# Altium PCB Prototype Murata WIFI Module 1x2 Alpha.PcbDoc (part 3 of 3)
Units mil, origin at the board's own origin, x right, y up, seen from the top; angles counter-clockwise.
Board outline 708.66 x 1594.49 mil, 6 copper layers (Component Side, Ground Plane (GND), Inner Layer 1, Inner Layer 2, Power Plane (VCC), Solder Side), stack 20.279 mil thick; 197 components, 116 nets, 943 pads, 479 vias.
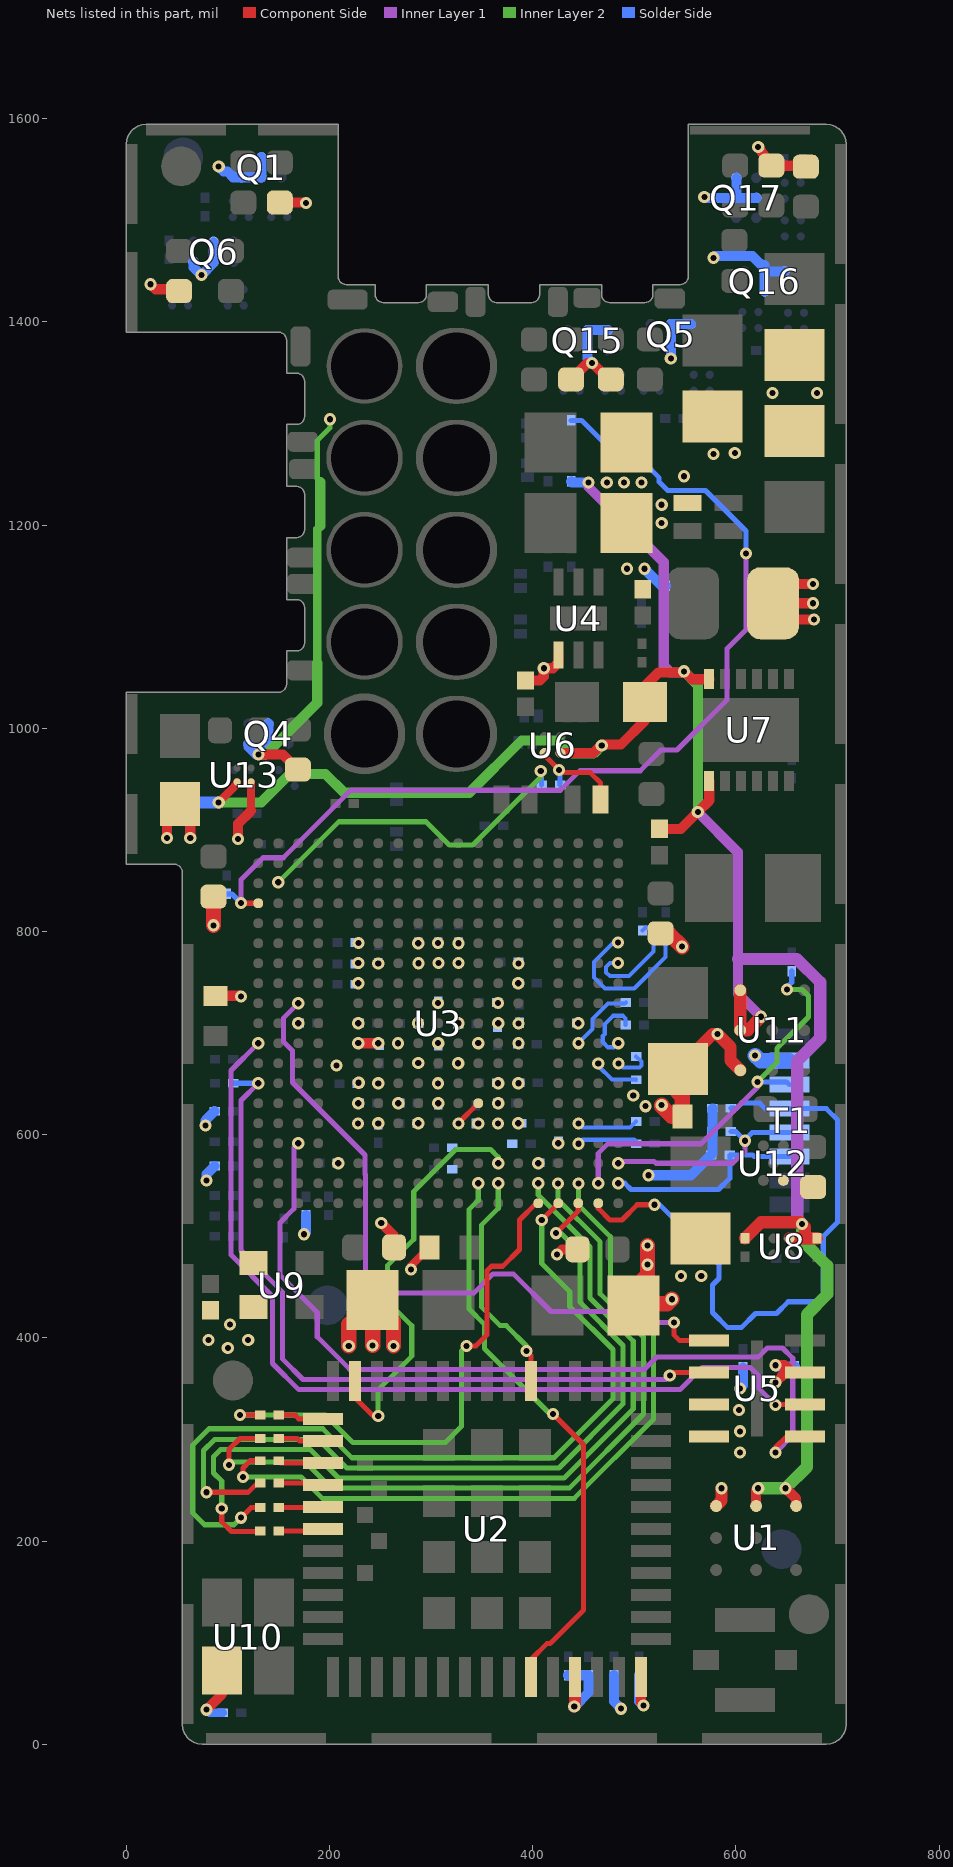
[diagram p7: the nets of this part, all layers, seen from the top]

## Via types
v1: diameter 12, hole 6, Component Side to Solder Side, tented both sides, 479 vias

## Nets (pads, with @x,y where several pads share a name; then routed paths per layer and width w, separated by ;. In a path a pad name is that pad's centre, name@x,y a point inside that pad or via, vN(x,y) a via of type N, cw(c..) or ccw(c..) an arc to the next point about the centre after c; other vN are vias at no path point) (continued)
RX_CLK_N: C54.2 U3.J1 | length 69.2
  Solder Side w4: v1(484.29,690) 480.29,686 474,686 469,691 469,697 471,699 471,709 479,717 489,717 491.54,714.46 C54.2@491.54,708
RX_CLK_P: C53.2 U3.J3 | length 69.1
  Solder Side w4: v1(445,690) 459,704 459,713.97 474.03,729 490.68,729 C53.2@491.68,730
RX_N: C49.2 U3.P1 | length 160.6
  Solder Side w4: v1(484,789) 479.38,789 460.36,769.97 460.36,754.67 471.03,744 500,744 530.94,774.94 C49.2@530.94,800.94
RX_P: C48.2 U3.N1 | length 111.1
  Solder Side w4: v1(484,769) 476.36,769 472.36,765 472.36,759.64 476,756 494.91,756 519,780.09 519,783 519,801 516,804 511.11,804 C48.2@508.06,800.94
SDIO_CLK: R1.1 U3.A3 | length 791
  Component Side w5: v1(79,248) 120,248 129,257 R1.1@131.94,257 ; v1(423,503) 444.88,524.88 U3.A3@444.88,532.48
  Inner Layer 2 w5: v1(79,248) 76,251 76,289 87,300 189,300 217,272 426,272 489,335 489,392.57 446.5,435.07 446.5,484.5 428,503 v1(423,503)
SDIO_CMD: R2.1 U3.B3 | length 736.5
  Component Side w5: v1(115,263) 115,272 122,279 R2.1@131.94,279
  Inner Layer 2 w5: v1(115,263) 172,263 193,242 441,242 519,320 519,405 476.5,447.5 476.5,499.5 445,531 v1(445,552)
SDIO_D0: R3.1 U3.A4 | length 829.4
  Component Side w5: v1(113,223) 123,233 R3.1@131.94,233 ; v1(409,516) 425.2,532.2 U3.A4@425.2,532.48
  Inner Layer 2 w5: v1(113,223) 106,216 77,216 65.5,227.5 65.5,294.5 81.5,310.5 193.5,310.5 222,282 421,282 479,340 479,388.43 436.5,430.93 436.5,445.64 409,473.14 v1(409,516)
SDIO_D1: R4.1 U3.B4 | length 762.5
  Component Side w5: v1(101,275) 101,290 112,301 R4.1@131.94,301
  Inner Layer 2 w5: v1(101,275) 104,278 176,278 202,252 436,252 509,325 509,400.86 466.5,443.36 466.5,494.5 425,536 v1(425,552)
SDIO_D2: R5.1 U3.A5 | length 519.4
  Component Side w5: v1(112,324) R5.1@131.94,324 ; v1(335,392) 344,392 355,403 355,452 355,455 355,466 359.5,470.5 370.5,470.5 387,487 387,516 403.48,532.48 U3.A5@405.51,532.48
  Inner Layer 2 w5: v1(112,324) 196,324 223,297 314,297 330,313 330,387 v1(335,392)
SDIO_D3: R6.1 U3.B5 | length 826
  Component Side w5: v1(94,232) 94,219 103.5,209.5 131.44,209.5 R6.1@131.94,210
  Inner Layer 2 w5: v1(94,232) 94,259 86,267 86,283 93,290 181,290 209,262 431,262 499,330 499,396.72 456.5,439.22 456.5,489.5 405.51,540.49 v1(405.51,552.17)
SPI_FLASH_CLK: R20.2 U3.G19 U5.6 | length 750.8
  Component Side w5: v1(535,363) 537.75,365.75 U5.6@573.76,365.75
  Inner Layer 1 w5: v1(129.92,650.59) 113,633.67 113,485.86 154,444.86 154,379 174,359 492,359 531,359 v1(535,363)
  Solder Side w5: R20.2@105.51,650.59 v1(129.92,650.59)
SPI_FLASH_CS_N: U3.D17 U5.1 | length 845.9
  Component Side w5: v1(639,287) 639,292 649.76,302.76 U5.1@668.24,302.76
  Inner Layer 1 w5: v1(169.29,591.54) 165,587.24 165,527 151.5,513.5 151.5,461.5 188,425 188,401 220,369 510,369 522,381 622,381 631,390 646,390 656,380 656,304 v1(639,287)
SPI_FLASH_MISO: U3.J19 U5.2 | length 909.4
  Component Side w5: v1@639.25,334.25 U5.2@668.24,334.25
  Inner Layer 1 w5: v1(129.92,689.96) 103,663.04 103,481.72 144,440.72 144,374.86 169.86,349 518.14,349 545,349 567,371 614,371 623,362 623,350 v1(639,334)
SPI_FLASH_MOSI: U3.L17 U5.5 | length 697.4
  Component Side w5: v1(539,415) 539,403 544.76,397.24 U5.5@573.76,397.24
  Inner Layer 1 w5: v1(169.29,729.33) 154.58,714.62 154.58,691.58 163.58,682.58 163.58,651.38 234.98,579.98 234.98,561 235.5,560.48 235.5,457.5 249,444 294,444 342,444 361,463 381,463 418,426 481,426 492,415 v1(539,415)
TCK: R32.1 T1.3 U3.B2 | length 400.1
  Inner Layer 1 w5: v1(464.57,552.17) 464.57,581.57 474,591 565.71,591 621.23,646.53 v1(621.23,652)
  Inner Layer 2 w5: v1(621.23,652) 640.31,671.07 640.31,684.69 671.5,715.88 671.5,736.5 665.06,742.94 v1(650.42,742.94)
  Solder Side w5: v1(621.23,652) 649.97,652 T1.3@652.76,649.21 ; v1(650.42,742.94) 650.42,745.42 655,750 R32.1@655,760.94
TDI: R28.2 T1.5 U3.C1 | length 205.5
  Inner Layer 1 w5: v1(484.25,571.85) 485.9,573.5 519.59,573.5 521.24,571.85 596.85,571.85 609,584 v1(609,594)
  Solder Side w5: R28.2@595.06,603 598.84,603 600,603 608.5,594.5 615.97,601.97 T1.5@652.76,601.97
TDO: R29.2 T1.6 U3.B1 | length 199.3
  Solder Side w5: v1(484.25,552.17) 490.73,552.17 496.9,546 523,546 583,546 594.06,557.05 R29.2@594.06,580.05 616.38,580.05 618.09,578.35 T1.6@652.76,578.35
TMS: R27.2 T1.4 U3.A2 | length 654.5
  Component Side w5: U3.A2@464.57,532.48 464.57,527.43 476,516 488,516 503,531 v1(520,531)
  Solder Side w5: v1(520,531) 525,531 583.5,472.5 583.5,458.5 576.96,451.96 576.96,425.04 592,410 605.38,410 619.38,424 640,424 651.5,435.5 678.5,435.5 686,443 686,499.77 700.1,513.87 700.1,614.59 689.1,625.59 T1.4@652.76,625.59 ; R27.2@595.06,626 600.71,626 605.71,631 623.5,631 629,625.5 652.67,625.5 T1.4@652.76,625.59 ; 677.59,625.59 T1.4@652.76,625.59
TX_CLK_N: C47.2 U3.H2 | length 45.3
  Solder Side w4: v1(464.57,670.03) 464.57,667.54 477.94,654.17 481,654.17 501.63,654.17 C47.2@501.8,654
TX_CLK_P: C46.2 U3.H1 | length 36.1
  Solder Side w4: v1(484.57,670.17) 488.73,666 505,666 507,668 507,671.8 C46.2@501.8,677
TX_N: C45.2 U3.E3 | length 61
  Solder Side w4: v1(445,611) 449,607 495.89,607 C45.2@501.89,613
TX_P: C43.2 U3.D3 | length 61.5
  Solder Side w4: v1(445,591) 449,595 500,595 501.98,593.02 C43.2@501.98,591
V1P2: C18.2 C19.2 C20.2 C21.2 C22.2 C23.2 C24.2 C25.2 C27.2 C28.2 C29.2 C30.2 C31.2 C32.2 C33.2 C78.2 U3.E8 U3.E14 U3.F7 U3.G6 U3.G10 U3.G14 U3.H9 U3.H11 U3.J8 U3.J10 U3.J12 U3.K9 U3.K11 U3.L10 U3.M6 U3.N9 U3.N10 U3.N11 U3.N14 U3.P9 U3.P10 U3.P11 U11.A1 | length 302.8
  Component Side w8: U3.N14@226.85,768.7 U3.N14@228.35,768.7
  Component Side w10: U3.G14@228.35,650.59 v1(228.8,651.04) ; U3.N14@228.35,768.7 v1(228.35,768.85) ; C32.2@519.6,664.6 C32.2@543,664.6
  Component Side w12: C32.2@543,664.6 577.36,698.95 v1(582.05,698.95) 594.86,686.14 594.86,672.86 602,665.72 U11.A1@604.33,663.39 U11.A1@604,663.72
  Component Side w15: v1(513,491) v1(513,472) 513,462 499.4,448.4 C78.2@499.4,432 500.9,433.5 532.5,433.5 v1(537,438) ; v1(527,629) 527,628 537,618 C31.2@547.32,618 547.32,637 543,641.32 C32.2@543,664.6
  other v1: 228,611 346.46,611.04 511,628 366.09,630.91 499,638.67 307,650.5 385.91,650.59 207,668 287.4,670.4 326.72,670.28 267.54,689.96 307.05,690 346.5,690 287.15,709.65 326.85,709.65 307,729.42 385.81,749 287.7,768.7 307.39,769 327,768.93 287.4,788.4 307,788.47 326.89,788.39
V1P8: C1.2 C26.2 C51.2 C73.2 C74.2 C75.2 U1.A1 U2.38 U3.E7 U3.E9 U3.F8 U10.4 | length 196.3
  Component Side w5: U3.E9@327.05,611.5 U3.F8@346.46,630.91
  Component Side w10: v1(79,34) 94.41,49.41 U10.4@94.41,72.54 ; U3.E9@326.77,611.22 327.05,611.5 U3.E9@327.05,611.22
  Component Side w12: v1(441,37) 441.61,37.61 U2.38@441.61,66.33 ; U1.A1@580.63,234.5 586,239.87 v1(586,252)
  Solder Side w8: v1(79,34) 82,31 C1.2@94.94,31
  Solder Side w10: C74.2@435,67.94 C75.2@455,67.94 455,51 v1(441,37)
  other v1: 327,611 366,611
V1P8_19P2MHZ: U2.36 U3.B8 | length 558.1
  Component Side w5: U2.36@398.31,66.33 398.31,83.31 414,99 417,99 450,132 450,295 v1(420,325)
  Inner Layer 2 w5: v1(346.46,552.17) 346.46,535.46 337.5,526.5 337.5,428.36 352.5,413.36 352.5,389.5 v1@417,325
V2P5: C59.2 C63.2 C64.2 C65.2 C82.2 L5.2 U3.E6 U3.G7 U3.J6 U12.C3 | length 29.3
  Component Side w10: v1(251,513) 263.69,500.31 C59.2@263.69,489
  other v1: 546,461 566,461 385.83,611.17 366.09,650.59 385.96,689.96
V3P3: C2.2 C3.2 C4.2 C5.2 C6.2 C7.2 C12.1 C13.1 C15.1 C16.2 C17.1 C34.2 C35.2 C36.2 C37.2 C38.2 C44.2 C55.2 C56.2 C57.2 C58.2 C60.2 C61.2 C62.2 C66.2 C67.2 C68.2 C69.2 C70.2 C71.2 C72.2 C95.2 L1.1 R22.1 R26.2 R27.1 R28.1 R29.1 R34.2 T1.2 U2.41 U3.C5 U3.C15 U3.D4 U3.E11 U3.E13 U3.F10 U3.F12 U3.F14 U3.G13 U3.J13 U3.J14 U3.K3 U3.K6 U3.K7 U3.K14 U3.K17 U3.L7 U3.M14 U3.N6 U3.N13 U3.P14 U4.4 U5.3 U5.7 U5.8 U9.1 U9.4 U13.A1 | length 1041
  Component Side w8: 122.89,918.89 U13.A1@122.89,947.11 ; v1(280.32,467.32) 280.32,471 C37.2@298.32,489
  Component Side w10: v1(40,892) 40,912.54 C95.2@53,925.54 63,915.54 v1(63,892) ; C16.2@88,736.68 112.32,736.68 v1(113,736) ; v1(110,891) 110,906 122.89,918.89 ; U3.J14@228.35,689.96 v1(248,689.99) ; v1(248.03,611.16) v1(248.03,611.16) ; v1(366,729.47) U3.L7@366.14,729.33 ; U3.K6@385.83,709.65 v1(385.97,709.5) ; U3.N6@385.83,768.7 v1(386,768.53) ; C2.2@393,1046.99 406.99,1046.99 411,1051 v1(411,1059) 420,1059 425.32,1064.32 U4.4@425.32,1072.17 U4.4@425.32,1067.32 ; v1(424,482) 429,487 C61.2@444.31,487 ; v1@506.57,40.43 U2.41@506.57,66.33 ; v1(639,356) 648.75,365.75 U5.3@668.24,365.75 655.25,365.75 648,373 v1(639,373) ; v1(676,1123) L1.1@636.76,1123 ; v1(676,1142) 655.76,1142 L1.1@636.76,1123 ; v1(677,1107) 652.76,1107 L1.1@636.76,1123
  Component Side w15: v1(85.91,806) C60.2@85.91,834.31 ; v1(219,392) 219,413.4 C38.2@242.6,437 ; v1(242.4,392.4) 242.6,392.4 C38.2@242.6,437 ; v1(263,392) 263,416.6 C38.2@242.6,437 ; C72.2@526,798.12 533.88,798.12 v1(547,785)
  Solder Side w10: v1(78,609) 78,614.06 R34.2@86.94,623 R34.2@86.8,623 ; v1(79,555) 79,561.05 R22.1@86.94,569 ; v1(175,502) 177,504 R26.2@177,520.94 ; C56.2@480,67.94 480,42 v1(487,35) ; C55.2@505,67.94 505,42 v1(509,38) ; v1(514,560) 555.89,560 R29.1@575.94,580.05 576.94,581.06 R28.1@576.94,603 576.94,625.27 R27.1@577.31,625.63 ; v1(604,350) 607,353 C13.1@607,370.94 ; v1(639,373) 640.06,371.94 C12.1@658,371.94
  Solder Side w15: v1(619,678) 624.17,672.83 T1.2@652.76,672.83
  other v1: 604,287 604,308 603,329 100,390 81,398 120,398 102,413 208.66,571.85 405.51,571.85 425.2,591.54 287.4,611.22 228.35,630.91 267.72,630.91 307.09,630.91 248.03,650.53 228.39,690 169.29,709.65 228.35,709.65 366.14,709.64 444.88,709.65 228.36,749 248.03,768.53 228.46,788.5
V3P3_ALWAYS: C41.2 C42.2 C52.2 C77.2 C94.2 R15.2 U1.A2 U1.A3 U6.A2 U7.1 U7.12 U8.A2 U11.A2 U11.A3 U13.A2 | length 2236.6
  Component Side w8: v1(91,927) 109.11,945.11 U13.A2@109.11,947.11
  Component Side w10: U6.A2@427.47,975.63 459.63,975.63 468,984 487,984 510.46,1007.46 C52.2@510.46,1026 510.46,1041.46 524,1055 548,1055 v1(549,1056) 556.77,1048.23 U7.12@573.82,1048.23 ; C77.2@525,900.99 546.08,900.99 v1(562.59,917.5) 573.82,928.73 U7.1@573.82,947.84 ; U1.A2@620,234.5 v1@620,250 ; v1(649,252) 659.37,241.63 U1.A3@659.37,234.5
  Component Side w12: U11.A3@604.33,742.13 U11.A2@604.33,702.76 611.76,702.76 v1@624.73,715.73 ; C42.2@609,498.06 624.74,513.8 v1@663.2,513.8 ; U8.A2@653.06,498.06 668,498.06 ; v1@668,509 668,498.06 ; C41.2@680,498.06 668,498.06
  Inner Layer 1 w10: v1(455,1242) 455,1237.37 529,1163.37 529,1061.37 535.37,1055 548,1055 v1(549,1056) ; v1(562.59,917.5) 602,878.09 602,773 602,738.73 v1(624.73,716)
  Inner Layer 1 w12: 602,773 660,773 683,750 683,695 660.5,672.5 660.5,516.5 v1(665,512)
  Inner Layer 2 w10: v1(91,927) 133,927 161,955 196,955 214.44,936.56 337.56,936.56 389,988 426,988 439,975 460,975 v1(468,983) ; v1@548,1055 v1(549,1056) 562.59,1042.41 v1(562.59,917.5)
  Inner Layer 2 w12: v1(622,252) v1(649,252) 670,273 670,423 690,443 690,471 665,496 v1(665,512)
  Solder Side w10: R15.2@438,1242.94 438.94,1242 v1(455,1242)
  Solder Side w12: C94.2@70.06,927 v1(91,927)
V28P0: C8.2 C9.2 C10.2 C11.2 C39.2 C40.2 D1.2 Q1.2 Q1.3 Q1.6 Q4.2 Q4.3 Q4.6 Q5.2 Q5.3 Q5.6 Q6.2 Q6.3 Q6.6 Q15.2 Q15.3 Q15.6 Q16.2 Q16.3 Q16.6 Q17.2 Q17.3 Q17.6 R9.1 R13.1 R17.1 R18.1 R19.1 R53.1 R54.1 R55.1 | length 1052.9
  Component Side w10: v1(24,1437) 28.87,1432.13 50.2,1432.13 R19.1@52.01,1430.32 ; v1(130.14,974.2) 154.11,974.2 R17.1@169,959.32 ; R9.1@151.13,1517.44 176.56,1517.44 v1(177,1517) ; R53.1@436.69,1343.32 R53.1@437.95,1343.32 454.23,1359.6 v1(458.5,1359.6) 470.7,1347.4 R18.1@476.9,1347.4 ; v1(622,1572) R55.1@635,1553.68 R54.1@668,1553.68
  Inner Layer 2 w5: 191,1242.4 188,1245.4 188,1283.16 200.5,1295.66 v1(200.5,1304.15)
  Inner Layer 2 w8: 188.03,1064 188.03,1196.17
  Inner Layer 2 w10: v1@130.44,974.2 137.2,974.2 188.03,1025.03 188.03,1064 ; 191,1199.15 191,1242.4
  Solder Side w10: Q6.2@66.23,1459.16 66.23,1453.78 v1(74,1446) 85.91,1457.91 Q6.3@85.91,1459.16 ; Q6.3@86,1458.16 Q6.6@86,1477.84 ; v1(91,1553) 96,1548 99.63,1548 105.34,1542.28 Q1.2@113.44,1542.28 Q1.3@133.13,1542.28 Q1.6@133.13,1561.97 ; Q4.2@120.32,984.84 120.32,981.59 v1@127.7,974.2 ; v1@129.75,974.59 Q4.3@140,984.84 Q4.6@140,1004.53 ; v1(458.5,1359.6) 454.06,1364.04 Q15.6@454.06,1372.16 Q15.3@454.06,1391.84 Q15.2@473.75,1391.84 ; v1(510,1157) 526.94,1140.06 R13.1@531,1140.06 ; v1(536,1364) 536.08,1364.08 Q5.6@536.08,1378.16 Q5.3@536.08,1397.84 Q5.2@555.77,1397.84 ; v1(569,1523) 570,1522 Q17.3@600.51,1522 ; v1(578,1463) 579.8,1464.8 606,1464.8 ; 600,1464.8 606,1464.8 ; Q17.2@600.51,1541.68 Q17.3@600.51,1522 ; Q17.6@620.19,1522 Q17.3@600.51,1522 ; Q16.6@628.32,1430 Q16.3@628.32,1449.68 ; 628.32,1455.68 Q16.3@628.32,1452.68 ; Q16.2@648,1449.68 Q16.3@628.32,1449.68 ; 606,1464.8 616.2,1464.8 Q16.3@628.32,1452.68 ; Q16.3@628.32,1449.68 Q16.3@628.32,1452.68
  other v1: 493,1157 527,1202 527,1220 473,1242 490,1242 507,1242 549,1248 578,1270 599,1271 636,1330 680,1330
WAKE_RX: R64.2 U3.U18 | length 340.4
  Inner Layer 2 w5: v1(149.61,848.39) 209.21,908 295,908 318,885 341,885 408,952 v1(408,958)
  Solder Side w5: R64.2@408.89,944 v1@408.89,958
WAKE_RX_PWR: D3.1 R64.1 U6.B2 | length 100.3
  Component Side w5: U6.B2@411.72,975.63 411.72,973.28 413.5,971.5 413.59,971.5 426,959.09 v1(426,959) 428.72,956.28 456.72,956.28 466.78,946.22 D3.1@466.78,930
  Solder Side w5: v1(426,959) 427,958.09 R64.1@427,944
WAKE_TX: R36.2 R63.2 U3.T19 | length 1002.5
  Component Side w5: v1@113.24,827.76 U3.T19@129.92,827.76
  Inner Layer 1 w5: v1(113,828) 113,851 134.5,872.5 154.59,872.5 221.09,939 427.3,939 446.49,958.2 506,958.2 526.3,978.5 542,978.5 591.5,1028 591.5,1078.5 610,1097 v1(610,1172)
  Solder Side w5: R63.2@99,836.94 104.06,836.94 v1(113,828) ; R36.2@438,1303.06 448,1303.06 490.06,1261 510,1261 524.5,1246.5 524.5,1242.41 532.91,1234 570.07,1234 610,1194.07 v1(610,1172)
WIFI_SDIO_CLK: R1.2 U2.19 | length 44.2
  Component Side w5: R1.2@150.06,257 191.89,257 U2.19@193.58,255.31
WIFI_SDIO_CMD: R2.2 U2.18 | length 44.4
  Component Side w5: R2.2@150.06,279 152.09,276.96 U2.18@193.58,276.96
WIFI_SDIO_D0: R3.2 U2.20 | length 43.8
  Component Side w5: R3.2@150.06,233 192.93,233 U2.20@193.58,233.65
WIFI_SDIO_D1: R4.2 U2.17 | length 44.5
  Component Side w5: R4.2@150.06,301 168,301 170.39,298.61 U2.17@193.58,298.61
WIFI_SDIO_D2: R5.2 U2.16 | length 45.1
  Component Side w5: R5.2@150.06,324 166,324 169.73,320.27 U2.16@193.58,320.27
WIFI_SDIO_D3: R6.2 U2.21 | length 44.4
  Component Side w5: R6.2@150.06,210 191.58,210 U2.21@193.58,212
WLAN_EN: U2.14 U3.C7 | length 405.8
  Component Side w5: U2.14@225.08,357.67 225.08,341.01 243.09,323 v1(248,323)
  Inner Layer 2 w5: v1(248,323) 248,349 281,382 281,412 257,436 257,471 283,497 283,544 324.35,585.35 358.65,585.35 366.14,577.86
  other v1: 366.14,571.85
WLAN_IRQ: U2.6 U3.B7 | length 219
  Component Side w5: U2.6@398.31,357.67 398.31,382.69
  Inner Layer 2 w5: v1(366.14,552.17) 366.14,527.5 349.5,510.86 349.5,430.5 368,412 374,412 394,392 v1(394,387)
pads on no net: U1.B1 U1.C1 U1.C2 U1.C3 U2.1 U2.2 U2.8 U2.9 U2.10 U2.11 U2.12 U2.13 U2.25 U2.31 U2.32 U2.39 U2.40 U2.43 U2.44 U2.45 U2.46 U2.51 U2.52 U2.65 U2.66 U2.67 U2.68 U2.69 U3.A8 U3.A9 U3.A11 U3.A12 U3.A13 U3.A14 U3.A15 U3.A16 U3.A17 U3.B9 U3.B10 U3.B11 U3.B12 U3.B13 U3.B14 U3.B15 U3.B16 U3.B17 U3.C2 U3.C9 U3.C10 U3.C11 U3.C12 U3.C13 U3.C14 U3.D1 U3.D2 U3.D18 U3.E1 U3.E2 U3.E17 U3.E18 U3.F1 U3.F3 U3.F17 U3.F19 U3.G1 U3.G2 U3.G3 U3.G17 U3.H3 U3.H7 U3.H14 U3.H17 U3.H18 U3.H19 U3.J2 U3.J17 U3.J18 U3.K2 U3.K18 U3.L1 U3.L2 U3.L3 U3.L6 U3.L14 U3.L18 U3.L19 U3.M1 U3.M2 U3.M3 U3.M7 U3.M13 U3.M17 U3.M18 U3.M19 U3.N2 U3.N3 U3.N17 U3.N19 U3.P3 U3.P6 U3.P19 U3.T10 U3.U10 U3.U19 U3.V6 U3.V7 U3.V8 U3.V9 U3.V12 U3.V13 U3.V14 U3.V15 U3.V18 U3.V19 U3.W5 U3.W6 U3.W8 U3.W9 U3.W11 U3.W12 U3.W14 U3.W15 U4.2 U4.5 U7.8

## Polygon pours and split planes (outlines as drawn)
V1P2 on Component Side "0" (solid, remove dead copper, pour order 14): 553,691 530,691 522,691 516,691 512,687 493,668 493,648 493,627 496,624 514,606 538,606 557,606 558,607 559,608 559,621 559,631 566,638 567,639 572,639 574,641 576,643 576,657 579,660 593,660 605,660 607,662 608,663 608,667 608,670 603,675 602,676 602,685 602,687 595,694 584,705 580,705 567,705 566,704
V3P3 on Component Side "0" (solid, remove dead copper, pour order 15): 561,353 589,353 595,353 599,357 607,357 609,357 611,355 611,345 611,283 609,281 606,278 599,278 571,278 563,286 553,296 553,300 553,351 555,353
V28P0 on Component Side "TopLayer-No Net" (solid, remove dead copper, pour order 21): 632,1395 673,1395 689,1395 691,1393 692,1392 692,1293 692,1267 687,1262 685,1260 632,1260 586,1260 572,1246 572,1237 572,1216 568,1212 567,1211 539,1211 538,1211 535,1208 535,1174 525,1164 524,1163 524,1130 520,1130 514,1124 502,1124 497,1124 477.17,1143.83 475,1146 475,1163 472,1163 462,1173 459,1176 459,1200 459,1306 445,1320 444,1320 381,1320 368,1333 368,1343 368,1359 372,1363 374,1365 389,1365 442,1365 446,1369 449,1369 529,1369 549,1349 554,1344 567,1344 602,1344 608,1350 615,1357 615,1367 615,1390 620,1395
V2P5 on Component Side "Component Side-No Net" (solid, pour order 18): 545,450 575,450 594,469 595,470 595,494 595,500 613,518 621,526 667,526 682,526 689,533 689,558 686,561 645,561 642,558 640,556 640,545 638,543 623,543 612,543 606,537 598,529 559,529 534,529 531,526 531,464 543,452
V3P3 on Component Side "0" (solid, remove dead copper, pour order 17): 148,486 148,407.5 148,391.5 142,385.5 139.5,383 107.5,383 85,383 79,389 75.5,392.5 75.5,423 75.5,437.5 76,438 76.5,438.5 81.5,438.5 105.5,438.5 108,441 110,443 110,455.5 110,484.5 112.5,487 113,487.5 136.5,487.5 146.5,487.5 148,486
V1P8 on Solder Side "0" (solid, remove dead copper, pour order 16): 366,623 323,623 321,621 313,613 308,613 308,567 294,553 279,538 279,527 279,468 115,304 69,258 69,52 69,28 72,25 81,16 91,16 94,16 100,22 101,23 101,33 101,43 105,47 106,48 172,48 423,48 428,43 429,42 429,34 434,29 445,29 451,29 456,34 463,41 463,53 463,70 459,74 427,74 418,74 413,79 395,97 393,97 393,127 439,173 489,223 576,223 596,243 596,250 596,269 564,301 354,511 354,536 337,553 337,556 337,576 339,578 342,581 351,581 381,581 385,585 385,594 385,599 382,602 376,608 376,618 371,623 370,623
V1P2 on Inner Layer 1 "0" (solid, remove dead copper, pour order 19): 557,424 500,424 486,438 467,438 419,438 395,462 382,475 360,475 288,475 273,490 247,516 247,521 247,576 232,591 189,634 189,655 189,774 214,799 221,806 262,806 321,806 335,820 337,822 411,822 476,822 522,776 607,691 607,686 607,649 593,635 559,601 545,601 469,601 456,588 453,585 453,573 453,543 462,534 484,512 516,512 519,512 541,490 557,474 557,440
V2P5 on Inner Layer 2 "0" (solid, remove dead copper, pour order 20): 525,450 529,446 555,446 567,446 572,451 578,457 578,458 578,466 587,475 588,476 588,509 588,717 529,776 510,795 449,795 431,795 417,809 353,873 302,873 226,873 183,830 144,791 144,731 144,494 161,477 165,473 211,473 231,473 251,493 265,507 265,525 265,551 291,577 318,604 372,604 381,595 413,563 434,563 445,563 475,533 490,518 490,476 490,478
GND on Ground Plane (GND) (split plane): 461 vertices, not listed, extent 10.09,10.09 698.57,1584.4
V3P3 on Power Plane (VCC) (split plane): 173 vertices, not listed, extent 10.09,10.09 698.57,1208.91
V28P0 on Power Plane (VCC) (split plane): 320 vertices, not listed, extent 10.09,1153.09 698.57,1584.4

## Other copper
Component Side:
  text "Top" at 319,-400 h60
Inner Layer 1:
  text "SIG1_LAYER3" at 100,-200 h60
Inner Layer 2:
  text "SIG2_LAYER4" at 100,-200 h60
Solder Side:
  text "Bottom" at 343,-419 h60
Ground Plane (GND) (plane layer: these items are gaps in the copper):
  lines w10: 561,135 652,135 657,130 657,8 654,5 562,5 561,6 561,134 562,135 567,135 568,134 568,11 650,11 650,130 649,131 576,131 574,129 574,20 575,19 643,19 643,125 581,125 581,23 580,22 633,22 636,25 636,120 635,121 593,121 589,117 589,28 628,28 629,29 629,114 627,116 597,116 597,34 621,34 622,35 622,109 621,110 606,110 606,40 613,40 614,41 614,108
  text "GND_LAYER2" at 100,-200 h60
Power Plane (VCC) (plane layer: these items are gaps in the copper):
  lines w10: 561,36 561,7 565,11 654,11 655,11 657,13 657,38 ; 561,135 652,135 657,130 657,38 ; 651,129 651,39 650,39 646,35 646,132 638,132 638,37 641,34 633,34 633,131 626,131 625,130 625,37 627,35 621,35 619,33 619,130 620,131 613,131 612,132 612,36 614,34 613,33 606,33 607,34 607,130 606,131 600,131 600,35 593,35 593,129 594,130 587,130 586,131 586,36 587,35 581,35 580,36 580,129 582,131 575,131 575,37 577,35 570,35 569,36 569,133 567,135 562,135 561,134 561,38 568,31 650,31 ; 661,4 657,8 657,30 653,26 653,18 652,19 567,19 567,25 568,26 649,26 650,25 650,31 ; 650,31 657,38 ; 650,31 657,38
  lines w20: 175.59,1220 176.59,1219 258,1219 ; 195,1219 403,1219 479,1143 535.12,1143 543.12,1151 707.78,1151
  text "PWR_LAYER5" at 100,-200 h60

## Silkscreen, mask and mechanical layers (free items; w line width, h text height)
Top Overlay:
  text "A" at 606,1235 h14
  text "K" at 520,1231 h14
  text "A" at 522,1177 h14
  text "K" at 594,1162 h14
  text "A" at 364,950 h14
  text "K" at 413,948 h14
  text "A" at 479,924 h14
  text "Top Overlay" at 77,-454 h60
Bottom Overlay:
  text "Murata WIFI Module" at 508,345 h20
  text "Rev 1.0" at 500,286 h20
  text "M" at 317,228 h100
  text "Bottom Overlay" at 19,-459 h60
Top Paste:
  text "Top Paste" at 100,-200 h60
Bottom Paste:
  text "Bottom Paste" at 0,-200 h60
Top Solder:
  text "Top Solder" at 100,-200 h60
Bottom Solder:
  text "Bottom Solder" at 0,-200 h60
Mechanical 1:
  lines w1: 0,866.14 0,1035.43 153.54,1035.43 157.93,1035.93 162.08,1037.38 165.82,1039.73 168.93,1042.84 171.28,1046.58 172.74,1050.74 173.23,1055.12 173.23,1370.08 172.74,1374.46 171.28,1378.62 168.93,1382.35 165.82,1385.47 162.08,1387.82 157.93,1389.27 153.54,1389.76 0.32,1389.76 0.32,1574.31 0.81,1578.7 2.26,1582.85 4.61,1586.59 7.73,1589.7 11.46,1592.05 15.62,1593.51 20,1594 208.66,1594 208.66,1440.94 209.15,1436.56 210.61,1432.41 212.96,1428.67 216.07,1425.56 219.81,1423.21 223.96,1421.75 228.35,1421.26 533.46,1421.26 537.85,1421.75 542,1423.21 545.74,1425.56 548.85,1428.67 551.2,1432.41 552.66,1436.56 553.15,1440.94 553.15,1594.49 688.98,1594.49 693.36,1594 697.52,1592.54 701.25,1590.19 704.37,1587.07 706.71,1583.34 708.17,1579.18 708.66,1574.8 708.66,19.68 cw(c688.98,19.68) 688.98,0 74.8,0 70.42,0.49 66.26,1.95 62.53,4.3 59.41,7.41 57.07,11.15 55.61,15.3 55.12,19.68 55.12,846.46 54.63,850.84 53.17,855 50.82,858.73 47.7,861.85 43.97,864.19 39.82,865.65 35.43,866.14 0,866.14
OUTLINE:
  lines w1: 157.9,1076.1 cw(c158,1076.1) 158,1076.2 ; 55.1,846.47 ccw(c55.12,846.47) 55.12,846.46 ; 55.12,846.46 55.12,19.68 55.61,15.3 57.07,11.15 59.41,7.41 62.53,4.3 66.26,1.95 70.42,0.49 74.8,0 688.98,0 693.36,0.49 697.52,1.95 701.25,4.3 704.37,7.41 706.71,11.15 708.17,15.3 708.66,19.68 708.66,1574.8 708.17,1579.18 706.71,1583.34 704.37,1587.07 701.25,1590.19 697.52,1592.54 693.36,1594 688.98,1594.49 553.15,1594.49 553.15,1445 cw(c544.75,1445) 544.75,1436.6 518.2,1436.6 518.2,1426.8 cw(c510.3,1426.8) 510.3,1418.9 475.8,1418.9 cw(c475.8,1426.8) 467.9,1426.8 467.9,1436.5 467.8,1436.6 406.9,1436.6 406.9,1427.1 cw(c398.7,1427.1) 398.7,1418.9 365.6,1418.9 cw(c365.6,1428) 356.5,1428 356.5,1436.6 295.5,1436.6 295.5,1427.1 cw(c287.3,1427.1) 287.3,1418.9 275.5,1418.9 253,1418.9 cw(c253,1426.8) 245.1,1426.8 245.1,1436.6 216.26,1436.6 cw(c216.26,1444.2) 208.66,1444.2 208.66,1594.49 19.13,1594.49 ccw(c19.13,1575.35) 0,1575.35 0,1574.8 0,1389.76 151.2,1389.76 cw(c151.2,1383.06) 157.9,1383.06 157.9,1349.4 167.6,1349.4 cw(c167.6,1341.4) 175.6,1341.4 175.6,1306.4 cw(c168.3,1306.4) 168.3,1299.1 157.9,1299.1 157.9,1238 168.5,1238 cw(c168.5,1231) 175.5,1231 cw(c175.5,1230.9) 175.6,1230.9 175.6,1195.3 cw(c167.9,1195.3) 167.9,1187.6 157.9,1187.6 157.9,1126.5 167.8,1126.5 cw(c167.8,1118.7) 175.6,1118.7 175.6,1083.5 cw(c168.3,1083.5) 168.3,1076.2 158,1076.2 ; 55.1,846.47 55.1,857.5 ccw(c46.5,857.5) 46.5,866.1 ccw(c46.46,866.1) 46.46,866.14 35.43,866.14 0,866.14 0,1035.43 150,1035.43 ccw(c150,1043.23) 157.8,1043.23 157.8,1076 cw(c158,1076) 158,1076.2
Mechanical 4:
  lines w1: -25,0 25,0 ; 0,-25 0,25
ASSY_TOP:
  text "ASSY TOP" at 120,-310 h60
ASSY_BOT:
  text "ASSY BOTTOM" at 720,-310 h60
Drill Drawing:
  lines w1: 55.12,-99.09 55.12,36 ; -275.59,1692.91 -382.41,1697.77 -275.59,1692.91 ; -275.59,1692.91 -137.8,1594.49 ; -275.59,1692.91 -137.8,1594.49 ; -137.8,1594.49 79.13,1594.49 -137.8,1594.49 ; 0,0 0,-135.09 0,0 ; 0,0 -157.48,0 0,0 ; 59.06,1791.34 59.06,1871.31 59.06,1791.34 ; 59.06,1791.34 175.7,1613.9 ; 59.06,1791.34 175.7,1613.9 ; 175.7,1613.9 175.6,1341.4 175.7,1613.9 ; 703.17,6.04 732.29,-150.67 ; 703.17,6.04 778.7,-134.31 ; 703.17,6.04 767.72,-177.17 ; 703.17,6.04 732.29,-150.67 ; 703.17,6.04 778.7,-134.31 ; 703.17,6.04 767.72,-177.17 ; 732.29,-150.67 778.7,-134.31 ; 732.29,-150.67 778.7,-134.31 ; 767.72,-177.17 854.85,-177.17 767.72,-177.17 ; -283.99,1389.76 153.54,1389.76 -283.99,1389.76 ; -270.19,866.14 35.43,866.14 -270.19,866.14 ; -264.3,1035.43 0,1035.43 -264.3,1035.43 ; 0,-158.71 0,866.14 0,-158.71 ; 208.66,1594.49 208.66,1713.83 208.66,1594.49 ; 553.15,1594.49 553.15,1713.83 553.15,1594.49 ; 708.66,1574.8 708.66,1713.83 708.66,1574.8
  lines w6: -1529.47,2450.38 -1529.47,3203.66 cw(c-1489.8,3203.66) -1489.8,3243.33 1106.53,3243.33 cw(c1106.53,3209.33) 1140.53,3209.33 ; -1529.47,2452.33 ccw(c-1495.47,2452.33) -1495.47,2418.33 ; -1499,2418.33 1096,2417.65 ; -1470.69,3050.65 1079.31,3050.65 ; -1466,3150 1084,3150 ; 1094.01,2417.65 ccw(c1094.01,2463.89) 1140.25,2463.89 ; 1140.53,2463.89 1140.53,3208.33
  text "6 Layers Stack Up" at -725,3175 h57
  text "FAB NOTES:" at 1271.32,3130.98 h60
  text "Layer" at -1466,3110 h24
  text "Gerber" at -566,3110 h24
  text "Copper" at 94,3110 h24
  text "Dielectric" at 594,3110 h24
  text "Name" at -1466,3070 h24
  text "Document" at -566,3070 h24
  text "Thickness" at 94,3070 h24
  text "Material" at 594,3070 h24
  text "Top Solder Mask" at -1466,2990 h34
  text "(.GTS)" at -566,2990 h34
  text "0.5mil" at 234,2990 h34
  text "Solder Resist" at 594,2990 h34
  text "1. Materials: Green clad, FR-4/Epoxy class,or equivalent.dielectric costant 4.2+/-0.2 ," at 1379,2985 h60
  text "Top" at -1466,2910 h34
  text "(.GTL)" at -566,2910 h34
  text "1.58mil" at -46,2910 h34
  text "3.5mil" at 234,2870 h34
  text "FR4" at 594,2870 h34
  text "see cross section for board thickness, copper" at 1539,2865 h60
  text "GND_IN2" at -1466,2830 h34
  text "(.GP1)" at -566,2830 h34
  text "0.65mil" at -46,2830 h34
  text "2.5mil" at 234,2790 h34
  text "FR4" at 594,2790 h34
  text "SIG1_IN3" at -1466,2750 h34
  text "(.G1)" at -566,2750 h34
  text "0.65mil" at -46,2750 h34
  text "weight and layer structures." at 1539,2745 h60
  text "2.5mil" at 234,2710 h34
  text "FR4" at 594,2710 h34
  text "SIG2_IN4" at -1466,2670 h34
  text "(.G2)" at -566,2670 h34
  text "0.65mil" at -46,2670 h34
  text "2.5mil" at 234,2630 h34
  text "FR4" at 594,2630 h34
  text "2. Components on the top and bottom layers." at 1359,2625 h60
  text "PWR_IN5" at -1466,2590 h34
  text "(.GP2)" at -566,2590 h34
  text "0.65mil" at -46,2590 h34
  text "3.5mil" at 234,2550 h34
  text "FR4" at 594,2550 h34
  text "Bottom" at -1466,2510 h34
  text "(.GBL)" at -566,2510 h34
  text "1.58mil" at -46,2510 h34
  text "3. Minimum signal trace width: 4 mils." at 1359,2505 h60
  text "Bottom Solder Mask" at -1466,2430 h34
  text "(.GBS)" at -566,2430 h34
  text "0.5mil" at 234,2430 h34
  text "Solder Resist" at 594,2430 h34
  text "4. Drilling:" at 1359,2385 h60
  text "Overall Thickness :21.26 mil+/-10%" at -1050,2270 h50
  text "4.1  minimum hole size is 6 mils drill." at 1519,2265 h60
  text "4.2  all plated holes are to be plated thru and with min .001 thick." at 1519,2145 h60
  text "4.3  all hole diameters are finished sizes." at 1519,2025 h60
  text "4.4  all holes to be +/-0.003 from true position unless" at 1519,1905 h60
  text "4.46" at 78.74,1889.76 h63 r90
  text "otherwise specified for PTH, or +/-0.002 if it's NPTH." at 1739,1805 h60
  text "5.3" at 236.22,1732.28 h63 r90
  text "14.05" at 551.18,1732.28 h63 r90
  text "18" at 728.35,1732.28 h63 r90
  text "4.5  NC drill file has been supplied, see hole size table." at 1519,1685 h60
  text "40.5" at -569.92,1666.23 h63
  text "5. Front to back pattern shall register within .005\"." at 1359,1565 h60
  text "6. Layer to layer(pattern to pattern) registration to be +/-.005\"." at 1359,1445 h60
  text "35.3" at -479.24,1361.95 h63
  text "7. Soldermask: Both sides of board, Liquid Photo Imageable, soldermask" at 1359,1325 h60
  text "over bare copper (SMOBC), green." at 1530,1200 h60
  text "8. Warpage and twist to meet IPC class II." at 1359,1085 h60
  text "26.3" at -450.87,1016.62 h63
  text "9. Silkscreen using white non-conductive epoxy or eqv." at 1359,965 h60
  text "22" at -431.18,859.14 h63
  text "10. Finish:" at 1319,825 h60
  text "10.1  Edge to be free of loose sliver and rough edge." at 1519,705 h60
  text "10.2  Finished board shall not have nicks scratches, voids," at 1519,585 h60
  text "exposed copper, poor plating or misdrilled holes." at 1850,480 h60
  text "10.3  Trace width tol=+/-.001\" of finished trace width." at 1519,365 h60
  text "11. Date code and UL rating shall be permanently marked or etched on PCB." at 1319,245 h60
  text "12. Remove non-functional pad on all inner layers and planes" at 1319,125 h60
  text "13. Impedance control:" at 1320,-20 h60
  text "0" at -216.54,-39.37 h63
  text "13.1 Differential pairs:" at 1530,-160 h60
  text "x10" at 1097,-214 h63
  text "R0.5" at 885.83,-216.54 h63
  text "1.4" at 102,-223 h63 r90
  text "0" at -19.68,-236.22 h63
  text "4/8 mils width/gap on  bottom and inner layers should be controlled 100 ohms +/- 10% ." at 1549,-305 h60
  text "unit:mm" at 166,-310 h63
  text "13.2 Single ended signals:" at 1550,-455 h60
  text "FAB DRAWING" at 47,-471 h75
  text "5 mils width on all layers should be controlled 50 ohms +/-10% ." at 1628,-602 h60
  text "14. This board use Via-in-Pad design for U3 component." at 1318,-735 h60
  text ".Legend" at 1317,-1414 h60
